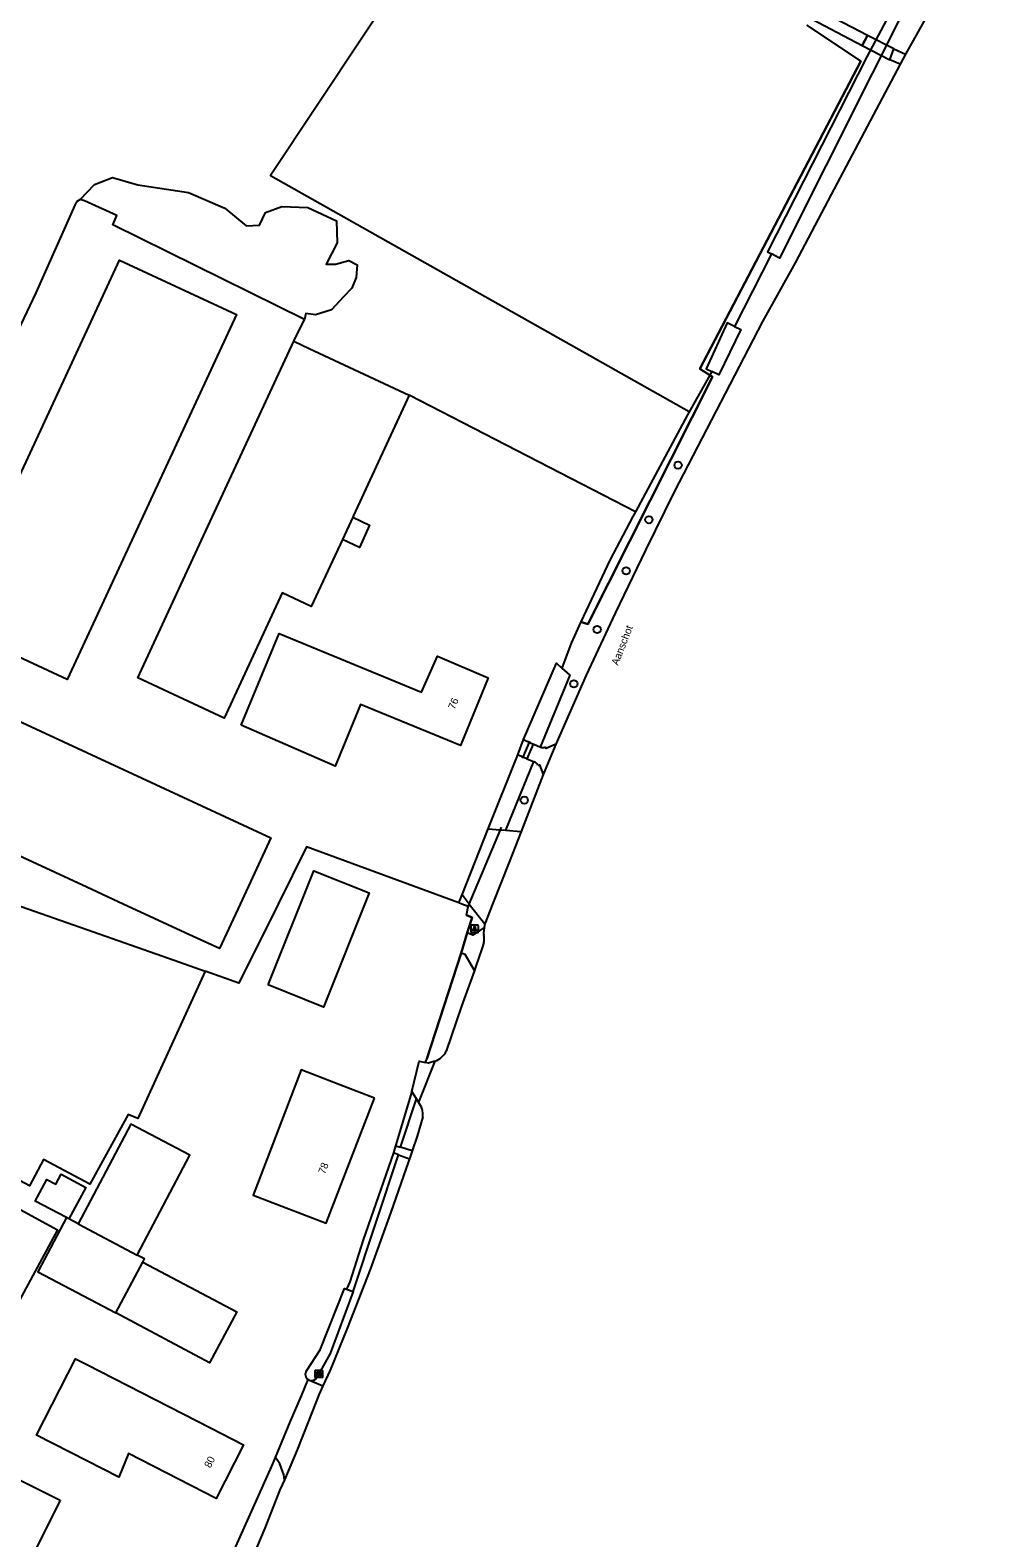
# Model space of a CAD drawing. Extents: x 159628 to 160723, y 388176 to 389416.
# Drawn here: x 160492.4 to 160620.6, y 388915 to 389117.2 of the extents above; entities that cross this region are included whole.
import ezdxf

# ---------------------------------------------------------------- set-up
doc = ezdxf.new("R2010")
doc.units = 0
for name, color, linetype in [('IMGEO_Berm_groen', 7, 'Continuous'), ('IMGEO_Boom', 7, 'Continuous'), ('IMGEO_Dek', 7, 'Continuous'), ('IMGEO_Duiker', 7, 'Continuous'), ('IMGEO_Erf', 7, 'Continuous'), ('IMGEO_Grasland_agrarisch', 7, 'Continuous'), ('IMGEO_Groenvoorziening', 7, 'Continuous'), ('IMGEO_Haag', 7, 'Continuous'), ('IMGEO_Hek', 7, 'Continuous'), ('IMGEO_Lichtpunt', 7, 'Continuous'), ('IMGEO_Openbare_ruimte_label', 7, 'Continuous'), ('IMGEO_Pand', 7, 'Continuous'), ('IMGEO_Pand_nummerreeks', 7, 'Continuous'), ('IMGEO_Rijbaan_lokaal_gesloten', 7, 'Continuous'), ('IMGEO_Rijbaan_lokaal_halfverhard', 7, 'Continuous'), ('IMGEO_Rijbaan_lokaal_open', 7, 'Continuous'), ('IMGEO_Rioolput', 7, 'Continuous'), ('IMGEO_Terreindeel_onvherhard', 7, 'Continuous'), ('IMGEO_Voetpad_halfverhard', 7, 'Continuous'), ('IMGEO_Voetpad_open', 7, 'Continuous'), ('IMGEO_Waterloop', 7, 'Continuous')]:
    doc.layers.add(name, color=color, linetype=linetype)

msp = doc.modelspace()

# ---------------------------------------------------------------- linework, layer by layer
at = {"layer": 'IMGEO_Berm_groen'}
for points in [[(160591.93, 389087.21), (160586.96, 389077.48)], [(160583.9, 389071.42), (160583.63, 389070.94)], [(160566.34, 389037.87), (160565.01, 389035.01), (160563.76, 389031.65)], [(160551.08, 388996.14), (160551.71, 388998.19), (160550.96, 388998.49), (160551.2, 388999.68)], [(160551.2, 388999.68), (160551.35, 388999.98)], [(160545.47, 388978.74), (160545.63, 388979.22), (160550.25, 388993.41)], [(160517.16, 388906.59), (160520.01, 388913.81), (160524.83, 388924.6), (160525.32, 388925.76)]]:
    msp.add_lwpolyline(points, dxfattribs=at)
at = {"layer": 'IMGEO_Boom'}
for centre in [(160579.37, 389058.88), (160575.46, 389051.55), (160572.41, 389044.69), (160568.51, 389036.82), (160565.37, 389029.54), (160558.73, 389013.93)]:
    msp.add_circle(centre, 0.489, dxfattribs=at)
at = {"layer": 'IMGEO_Dek'}
msp.add_lwpolyline([(160608.35, 389114.7), (160604.78, 389116.51), (160604.09, 389115.15), (160607.8, 389113.25)], close=True, dxfattribs=at)
at = {"layer": 'IMGEO_Duiker'}
for points in [[(160559.43, 389021.84), (160559.37, 389021.71), (160558.52, 389019.72), (160558.46, 389019.57)], [(160551.24, 388999.66), (160551.35, 388999.98), (160555.54, 389009.94), (160555.68, 389010.3)]]:
    msp.add_lwpolyline(points, dxfattribs=at)
at = {"layer": 'IMGEO_Erf'}
msp.add_lwpolyline([(160549.94, 389000.14), (160529.51, 389007.67), (160525.69, 389000), (160520.4, 388989.4), (160515.87, 388991)], dxfattribs=at)
at = {"layer": 'IMGEO_Grasland_agrarisch'}
for points in [[(160583.63, 389070.94), (160582.29, 389071.78), (160603.9, 389113.08), (160596.68, 389117.9)], [(160499.09, 389094.52), (160501.04, 389096.52), (160503.47, 389097.48), (160506.86, 389096.47), (160513.63, 389095.46), (160518.55, 389093.35), (160521.41, 389090.97), (160523.16, 389091.07), (160524, 389092.77), (160526.17, 389093.56), (160529.66, 389093.45), (160533.53, 389091.65), (160533.63, 389088.69), (160532.15, 389085.83), (160533.37, 389085.83), (160535.17, 389086.31), (160536.28, 389085.73), (160536.17, 389084.03), (160535.59, 389082.61), (160534.48, 389081.44), (160532.84, 389079.7), (160530.72, 389079.06), (160529.4, 389079.22), (160529.22, 389078.42)], [(160499.09, 389094.52), (160498.61, 389094.2), (160498.38, 389093.75), (160493.17, 389081.97), (160487.39, 389069.93), (160487.04, 389069.35), (160486.64, 389069.37)], [(160527.78, 389075.51), (160529.22, 389078.42)], [(160573.67, 389052.63), (160543.29, 389068.27)], [(160450.76, 389013.35), (160475.3, 389005.03), (160476.92, 389004.48), (160490.27, 389000), (160500, 388996.59), (160510.95, 388992.73), (160515.87, 388991)], [(160515.87, 388991), (160506.83, 388971.22), (160505.57, 388971.76), (160500.39, 388962.44), (160494.19, 388965.71), (160492.29, 388962.22), (160487.35, 388964.84), (160486.2, 388962.56), (160448.36, 388982.68), (160445.03, 388984.24)]]:
    msp.add_lwpolyline(points, dxfattribs=at)
at = {"layer": 'IMGEO_Groenvoorziening'}
for points in [[(160549.94, 389000.14), (160550.37, 389001.24)], [(160551.2, 388999.68), (160550.33, 389000), (160549.94, 389000.14)]]:
    msp.add_lwpolyline(points, dxfattribs=at)
at = {"layer": 'IMGEO_Haag'}
for points in [[(160543.64, 388974.85), (160541.46, 388967.58)], [(160542.11, 388967.37), (160544.28, 388973.85)], [(160541.17, 388966.62), (160537.1, 388954.96), (160535.29, 388949.3), (160534.88, 388948.34)], [(160535.76, 388948.03), (160541.85, 388966.37)]]:
    msp.add_lwpolyline(points, dxfattribs=at)
at = {"layer": 'IMGEO_Hek'}
for points in [[(160549.47, 389135.02), (160524.66, 389097.73), (160580.88, 389066.07)], [(160596.68, 389117.9), (160603.9, 389113.08), (160582.29, 389071.78), (160583.63, 389070.94)], [(160583.63, 389070.94), (160584.01, 389070.7), (160567.24, 389037.54), (160566.34, 389037.87)], [(160550.96, 388998.49), (160551.71, 388998.19), (160551.08, 388996.14), (160550.25, 388993.41), (160545.63, 388979.22)]]:
    msp.add_lwpolyline(points, dxfattribs=at)
at = {"layer": 'IMGEO_Lichtpunt'}
for p, q in [((160551.56, 388997.06), (160551.56, 388996.26)), ((160551.56, 388997.06), (160551.56, 388996.26)), ((160552.46, 388997.16), (160551.65, 388997.16)), ((160552.46, 388997.16), (160551.65, 388997.16)), ((160552.56, 388996.26), (160552.56, 388997.06)), ((160552.56, 388996.26), (160552.56, 388997.06)), ((160551.65, 388996.16), (160552.46, 388996.16)), ((160551.65, 388996.16), (160552.46, 388996.16))]:
    msp.add_line(p, q, dxfattribs=at)
for points in [[(160551.93, 388996.73), (160551.97, 388996.7), (160551.79, 388996.44), (160551.75, 388996.46), (160551.93, 388996.73)], [(160552.04, 388996.68), (160552.08, 388996.68), (160552.08, 388996.36), (160552.04, 388996.36), (160552.04, 388996.68)], [(160552.15, 388996.7), (160552.18, 388996.73), (160552.37, 388996.46), (160552.33, 388996.44), (160552.15, 388996.7)]]:
    msp.add_lwpolyline(points, dxfattribs=at)
msp.add_circle((160552.06, 388996.86), 0.0994, dxfattribs=at)
for centre, start, end in [((160551.65, 388997.06), 90, 180), ((160551.65, 388997.06), 90, 180), ((160552.46, 388997.06), 0, 90), ((160552.46, 388997.06), 0, 90), ((160551.65, 388996.26), 180, 270), ((160551.65, 388996.26), 180, 270), ((160552.46, 388996.26), 270, 0), ((160552.46, 388996.26), 270, 360)]:
    msp.add_arc(centre, 0.0946, start, end, dxfattribs=at)
at = {"layer": 'IMGEO_Pand'}
for points in [[(160500, 389076.9), (160504.4, 389086.39), (160520.09, 389079.1), (160500, 389035.82), (160497.36, 389030.13), (160481.67, 389037.42), (160500, 389076.9)], [(160534.31, 389048.9), (160532.67, 389045.38), (160530.14, 389039.92), (160526.23, 389041.75), (160518.44, 389024.95), (160506.83, 389030.34), (160515.4, 389048.8), (160527.78, 389075.51)], [(160527.78, 389075.51), (160529.85, 389074.54), (160543.29, 389068.27)], [(160543.29, 389068.27), (160535.81, 389052.14), (160535.69, 389051.88)], [(160535.69, 389051.88), (160537.97, 389050.82), (160536.59, 389047.84), (160534.31, 389048.9)], [(160535.69, 389051.88), (160534.31, 389048.9)], [(160520.73, 389024), (160525.82, 389036.29), (160544.91, 389028.4), (160547.08, 389033.23), (160553.9, 389030.34), (160550.15, 389021.27), (160536.73, 389026.75), (160533.32, 389018.48), (160520.73, 389024)], [(160513.2, 388996.15), (160504.87, 389000), (160500, 389002.25), (160472.03, 389015.19), (160478.91, 389030.06), (160500, 389020.31), (160524.69, 389008.89), (160520.58, 389000), (160517.81, 388994.02), (160513.2, 388996.15)], [(160524.36, 388989.14), (160530.47, 389004.46), (160537.9, 389001.5), (160531.79, 388986.17), (160524.36, 388989.14)], [(160538.62, 388973.97), (160533.95, 388975.76), (160528.79, 388977.75), (160522.33, 388960.96), (160532.15, 388957.17), (160538.62, 388973.97)], [(160506.76, 388952.91), (160513.83, 388966.31), (160505.93, 388970.49), (160498.85, 388957.09)], [(160497.26, 388957.93), (160493.05, 388960.15), (160494.62, 388963.06), (160495.83, 388962.41), (160496.57, 388963.76), (160499.86, 388961.99), (160497.58, 388957.76)], [(160490.56, 388959.27), (160496.05, 388956.31), (160489.13, 388943.47), (160482.76, 388946.9)], [(160497.26, 388957.93), (160493.42, 388950.66), (160503.9, 388945.14)], [(160497.58, 388957.76), (160497.26, 388957.93)], [(160498.85, 388957.09), (160497.58, 388957.76)], [(160498.85, 388957.09), (160506.76, 388952.91)], [(160503.9, 388945.14), (160507.54, 388951.98)], [(160507.54, 388951.98), (160520.12, 388945.29), (160516.48, 388938.45), (160503.9, 388945.14)], [(160507.54, 388951.98), (160507.76, 388952.39), (160506.76, 388952.91)], [(160500, 388938.23), (160516.6, 388929.72), (160521.05, 388927.44), (160517.36, 388920.24), (160505.58, 388926.28), (160504.29, 388923.12), (160500, 388925.32), (160493.26, 388928.77), (160498.5, 388938.99), (160500, 388938.23)], [(160496.43, 388920.01), (160486.82, 388900.78), (160480.17, 388904.11), (160489.78, 388923.33), (160496.43, 388920.01)]]:
    msp.add_lwpolyline(points, dxfattribs=at)
at = {"layer": 'IMGEO_Rijbaan_lokaal_gesloten'}
for points in [[(160620.56, 389133.18), (160616.91, 389126.58), (160609.9, 389114)], [(160609.9, 389114), (160609.19, 389112.66)], [(160609.19, 389112.66), (160599.94, 389095.19), (160595.11, 389086.03), (160590.72, 389078.15), (160578.84, 389055.28), (160574.98, 389047.48), (160570.95, 389039.03), (160567.05, 389030.7), (160562.98, 389021.45)], [(160562.98, 389021.45), (160561.27, 389017.39)], [(160561.27, 389017.39), (160558.31, 389009.71)], [(160558.31, 389009.71), (160556.69, 389005.61), (160554.47, 389000), (160553.42, 388997.34)], [(160553.36, 388996.85), (160553.26, 388996.09), (160553.3, 388995.77)], [(160553.42, 388997.34), (160553.36, 388996.85)], [(160553.29, 388994.84), (160553.03, 388993.98), (160552.23, 388991.65), (160552.03, 388991.09)], [(160552.03, 388991.09), (160550.29, 388986.28), (160548.26, 388980.25)], [(160546.73, 388978.92), (160544.53, 388973.44)], [(160545.12, 388971.45), (160544.33, 388968.84), (160543.67, 388966.88)], [(160543.67, 388966.88), (160543.31, 388965.82)], [(160543.31, 388965.82), (160543.2, 388965.48), (160540.81, 388958.67), (160538.04, 388950.98), (160534.99, 388943.2), (160532.66, 388937.48), (160531.69, 388935.36)], [(160531.69, 388935.36), (160531.13, 388934.15), (160529.75, 388930.63), (160528.26, 388926.79), (160526.52, 388922.78)], [(160526.52, 388922.78), (160525.93, 388921.41), (160523.89, 388916.29), (160518.83, 388904.33), (160515.37, 388896.26), (160513.19, 388891.13)]]:
    msp.add_lwpolyline(points, dxfattribs=at)
for centre, radius, start, end in [((160550.72, 388995.32), 2.62, 349.4527, 9.8032), ((160545.83, 388981.5), 2.73, 289.2657, 332.9469), ((160542.17, 388971.67), 2.95, 355.7154, 36.8514)]:
    msp.add_arc(centre, radius, start, end, dxfattribs=at)
at = {"layer": 'IMGEO_Rijbaan_lokaal_halfverhard'}
msp.add_lwpolyline([(160597.37, 389118.72), (160604.09, 389115.15), (160604.78, 389116.51), (160598.34, 389119.88)], dxfattribs=at)
at = {"layer": 'IMGEO_Rijbaan_lokaal_open'}
for points in [[(160557.85, 389020.01), (160558.6, 389022.08)], [(160558.6, 389022.08), (160559.37, 389021.71), (160559.91, 389021.46)], [(160559.91, 389021.46), (160559.07, 389019.48)], [(160560.85, 389021.03), (160560.58, 389021.15), (160559.91, 389021.46)], [(160562.98, 389021.45), (160561.65, 389020.85), (160561.56, 389021.08)], [(160559.07, 389019.48), (160558.52, 389019.72), (160557.85, 389020.01)], [(160559.07, 389019.48), (160559.95, 389019.1)], [(160559.95, 389019.1), (160560.05, 389019.06)], [(160560.57, 389018.57), (160560.78, 389018.66), (160561.27, 389017.39)], [(160550.37, 389001.24), (160553.88, 389010.07)], [(160553.88, 389010.07), (160554.95, 389009.99), (160555.54, 389009.94), (160556.19, 389009.89)], [(160556.19, 389009.89), (160558.31, 389009.71)], [(160551.35, 388999.98), (160550.37, 389001.24)], [(160551.35, 388999.98), (160553.42, 388997.34)], [(160553.36, 388996.85), (160551.82, 388995.84), (160551.08, 388996.14)], [(160550.25, 388993.41), (160551.08, 388996.14)], [(160552.03, 388991.09), (160550.78, 388993.23), (160550.25, 388993.41)], [(160543.64, 388974.85), (160544.63, 388978.9), (160545.47, 388978.74)], [(160546.73, 388978.92), (160545.89, 388978.66), (160545.47, 388978.74)], [(160544.28, 388973.85), (160543.64, 388974.85)], [(160544.53, 388973.44), (160544.28, 388973.85)]]:
    msp.add_lwpolyline(points, dxfattribs=at)
for centre, radius, start, end in [((160561.14, 389021.86), 0.884, 250.891, 298.1666), ((160559.85, 389018.34), 0.755, 18.0178, 74.6939)]:
    msp.add_arc(centre, radius, start, end, dxfattribs=at)
at = {"layer": 'IMGEO_Rioolput'}
for p, q in [((160530.65, 388936.54), (160530.65, 388937.39)), ((160530.72, 388937.47), (160531.57, 388937.47)), ((160531.57, 388936.47), (160530.72, 388936.47)), ((160531.13, 388937.25), (160531.16, 388937.25)), ((160531.16, 388936.69), (160531.13, 388936.69)), ((160531.65, 388937.39), (160531.65, 388936.54))]:
    msp.add_line(p, q, dxfattribs=at)
for points in [[(160530.65, 388936.54), (160530.65, 388937.39)], [(160530.72, 388937.47), (160531.57, 388937.47)], [(160531.57, 388936.47), (160530.72, 388936.47)], [(160531.23, 388937.16), (160530.98, 388937.17), (160530.98, 388936.77)], [(160530.98, 388936.77), (160531.11, 388936.77), (160531.11, 388936.93), (160531.12, 388936.93)], [(160531.16, 388937.09), (160531.11, 388937.09), (160531.11, 388937)], [(160531.11, 388937), (160531.16, 388937)], [(160531.16, 388936.9), (160531.24, 388936.77), (160531.37, 388936.77), (160531.31, 388936.89)], [(160531.65, 388937.39), (160531.65, 388936.54)]]:
    msp.add_lwpolyline(points, dxfattribs=at)
for centre, radius, start, end in [((160530.72, 388937.39), 0.0765, 91.552, 178.448), ((160530.72, 388937.39), 0.0765, 91.552, 178.448), ((160530.72, 388936.54), 0.0765, 181.552, 268.448), ((160530.72, 388936.54), 0.0765, 181.552, 268.448), ((160531.12, 388936.88), 0.0533, 26.0293, 88.6989), ((160531.17, 388936.99), 0.0964, 77.0061, 93.1865), ((160531.14, 388937.19), 0.19, 274.7715, 282.9687), ((160531.18, 388937.05), 0.0378, 276.6634, 79.6772), ((160531.23, 388937.05), 0.109, 350.3612, 89.416), ((160531.23, 388937.05), 0.112, 277.5842, 350.9817), ((160531.22, 388936.84), 0.108, 29.5134, 73.7905), ((160531.57, 388937.39), 0.0765, 1.552, 88.448), ((160531.57, 388937.39), 0.0765, 1.552, 88.448), ((160531.57, 388936.54), 0.0765, 271.552, 358.448), ((160531.57, 388936.54), 0.0765, 271.552, 358.448)]:
    msp.add_arc(centre, radius, start, end, dxfattribs=at)
for centre, major_axis, ratio, start_param, end_param in [((160531.13, 388936.97), (-0.387, 0.002), 0.722429, 4.712389, 7.853982), ((160531.16, 388936.97), (-0.39, 0.002), 0.717154, 1.570796, 4.712389)]:
    msp.add_ellipse(centre, major_axis=major_axis, ratio=ratio, start_param=start_param, end_param=end_param, dxfattribs=at)
at = {"layer": 'IMGEO_Terreindeel_onvherhard'}
msp.add_lwpolyline([(160529.22, 389078.42), (160503.48, 389091.09), (160504.05, 389092.37), (160499.68, 389094.34), (160499.09, 389094.52)], dxfattribs=at)
at = {"layer": 'IMGEO_Voetpad_halfverhard'}
msp.add_lwpolyline([(160609.19, 389112.66), (160607.8, 389113.25), (160608.35, 389114.7), (160609.9, 389114)], dxfattribs=at)
at = {"layer": 'IMGEO_Voetpad_open'}
for points in [[(160608.35, 389114.7), (160604.78, 389116.51), (160604.09, 389115.15), (160607.8, 389113.25), (160608.35, 389114.7)], [(160541.46, 388967.58), (160541.17, 388966.62)], [(160541.85, 388966.37), (160541.17, 388966.62)], [(160541.46, 388967.58), (160542.11, 388967.37)], [(160541.85, 388966.37), (160543.31, 388965.82)], [(160543.67, 388966.88), (160542.11, 388967.37)], [(160525.32, 388925.76), (160527.36, 388930.63), (160528.81, 388934.04), (160529.73, 388936.22)], [(160529.73, 388936.22), (160529.89, 388936.13)], [(160529.89, 388936.13), (160531.69, 388935.36)], [(160526.52, 388922.78), (160526.45, 388923.44), (160525.89, 388924.91), (160525.32, 388925.76)]]:
    msp.add_lwpolyline(points, dxfattribs=at)
at = {"layer": 'IMGEO_Waterloop'}
for points in [[(160610.39, 389124.37), (160604.71, 389113.66), (160591.37, 389087.5), (160591.93, 389087.21)], [(160611.67, 389123.85), (160592.99, 389086.66), (160591.93, 389087.21)], [(160586.96, 389077.48), (160585.98, 389077.96), (160583.13, 389071.79), (160583.9, 389071.42)], [(160586.96, 389077.48), (160587.81, 389077.07), (160584.83, 389070.99), (160583.9, 389071.42)], [(160566.34, 389037.87), (160567.24, 389037.54), (160584.01, 389070.7), (160583.63, 389070.94)], [(160583.63, 389070.94), (160580.62, 389065.61), (160573.67, 389052.63)], [(160573.67, 389052.63), (160573.32, 389051.98), (160570.19, 389046.13), (160566.34, 389037.87)], [(160558.6, 389022.08), (160563.04, 389032.29), (160563.76, 389031.65)], [(160563.76, 389031.65), (160564.83, 389030.69), (160560.85, 389021.03)], [(160553.88, 389010.07), (160557.85, 389020.01)], [(160559.95, 389019.1), (160556.19, 389009.89)], [(160529.47, 388937.4), (160531.31, 388940.21), (160534.61, 388948.44), (160534.88, 388948.34)], [(160535.76, 388948.03), (160532.69, 388939.71), (160530.89, 388936.47)], [(160534.88, 388948.34), (160535.76, 388948.03)]]:
    msp.add_lwpolyline(points, dxfattribs=at)
for centre, radius, start, end in [((160530.18, 388936.94), 0.848, 147.1926, 237.8856), ((160530.19, 388936.9), 0.819, 248.5712, 328.9499)]:
    msp.add_arc(centre, radius, start, end, dxfattribs=at)

# ---------------------------------------------------------------- texts
at = {"layer": 'IMGEO_Openbare_ruimte_label'}
msp.add_text('Aanschot', height=1, rotation=68.7198, dxfattribs=at).set_placement((160571.31, 389031.94))
at = {"layer": 'IMGEO_Pand_nummerreeks'}
for s, rotation, p in [('76', 67.5221, (160549.38, 389026.01)), ('78', 68.9497, (160531.96, 388963.69)), ('80', 62.8647, (160516.59, 388924.26))]:
    msp.add_text(s, height=1, rotation=rotation, dxfattribs=at).set_placement(p)

doc.saveas('drawing.dxf')
